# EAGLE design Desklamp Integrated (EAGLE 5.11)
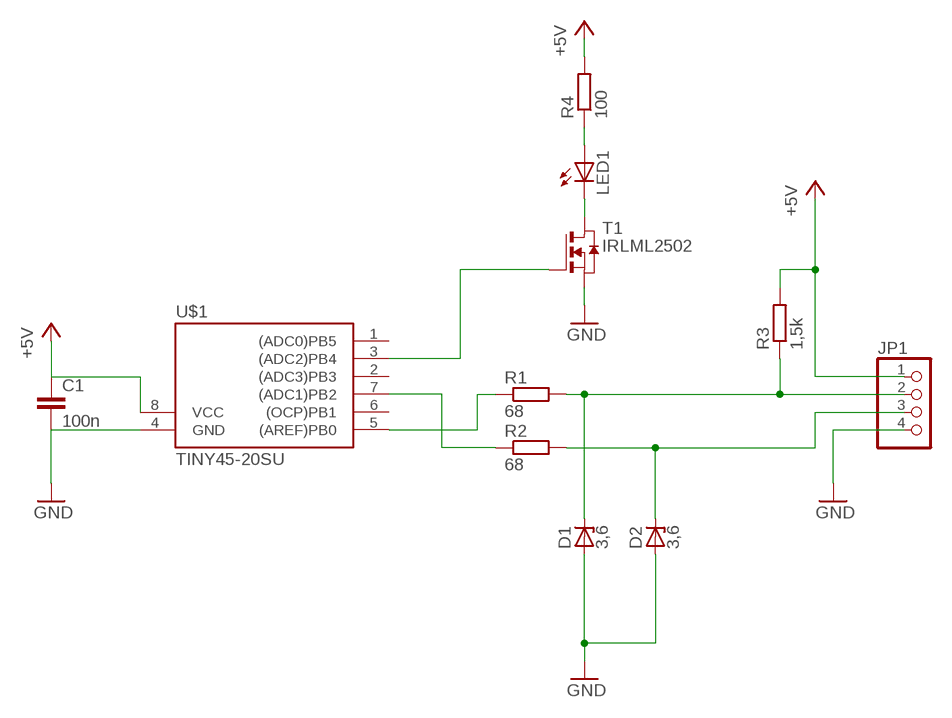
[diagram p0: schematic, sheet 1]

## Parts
C1  100n  C-EUC1206  [C1206]
D1  3,6  ZENER-DIODESOD80C  [SOD80C]
D2  3,6  ZENER-DIODESOD80C  [SOD80C]
JP1  PINHD-1X4  [1X04]
LED1  LED5MM  [LED5MM]
R1  68  R-EU_M1206  [M1206]
R2  68  R-EU_M1206  [M1206]
R3  1,5k  R-EU_M1206  [M1206]
R4  100  R-EU_M1206  [M1206]
T1  IRLML2502  NMOSSOT23  [SOT-23]
U$1  TINY45-20SU  TINY25/45/85-20SU  [SOIC8]

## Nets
+5V: C1.1 JP1.1 R3.2 R4.2 U$1.8(VCC)
GND: C1.2 D1.A D2.A JP1.4 T1.2(S) U$1.4(GND)
N$1: T1.3(G) U$1.3((ADC2)PB4)
N$2: LED1.K(C) T1.1(D)
N$3: LED1.A R4.1
N$6: R1.1 U$1.5((AREF)PB0)
N$7: D1.C JP1.2 R1.2 R3.1
N$8: D2.C JP1.3 R2.2
N$9: R2.1 U$1.7((ADC1)PB2)
Unconnected: U$1.1((ADC0)PB5) U$1.2((ADC3)PB3) U$1.6((OCP)PB1)

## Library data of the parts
C1 = rcl:C-EU: CAPACITOR, European symbol
D1 D2 = diode:ZENER-DIODE: Z-Diode
JP1 = pinhead:PINHD-1X4: PIN HEADER
LED1 = led:LED: LED
R1-R4 = rcl:R-EU_: RESISTOR, European symbol
T1 = zetex:NMOSSOT23: MOS FET; OC_FARNELL: unknown; OC_NEWARK: unknown
U$1 = avr-6:TINY25/45/85

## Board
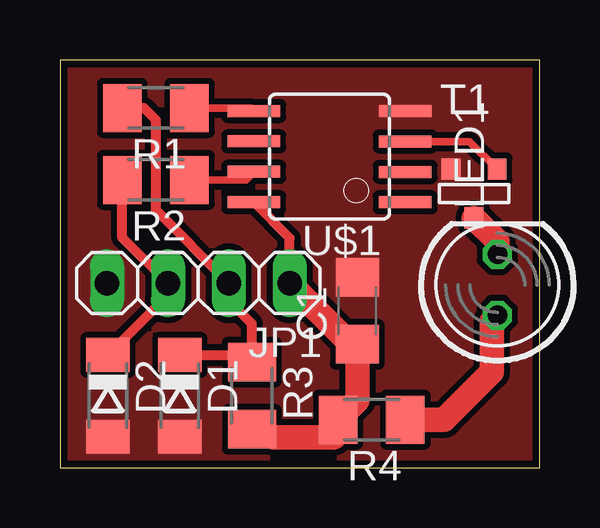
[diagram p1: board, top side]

Size 20 x 17 mm. Coordinates in mm from the lower left corner, seen from the top.
Outline: 0,0 20,0 20,17 0,17 0,0
Copper layers (1*16): Top 0.035mm / dielectric 1.5mm / Bottom 0.035mm
Design rules "PCB-POOL Standard": minimum track width 0.15mm, minimum drill 0.3mm, track to track 0.15mm, track to pad 0.15mm, pad to pad 0.15mm, via to via 0.15mm, smd to smd 0.15mm, copper to edge 0.3mm, drill to drill 0.2mm, minimum pad ring 0.2mm, minimum via ring 0.15mm, stop-mask expansion 0.075mm, vias tented up to drill 0mil, thermal gap 0.2mm

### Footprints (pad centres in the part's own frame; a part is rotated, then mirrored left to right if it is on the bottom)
C1206 = smd 1.6 x 1.8: 1 -1.4,0; 2 1.4,0
SOD80C = smd 1.4 x 1.8: A 1.7,0; C -1.7,0
1X04 = drill 1.016 long: 1 -3.81,0; 2 -1.27,0; 3 1.27,0; 4 3.81,0
LED5MM = drill 0.813 octagon: A -1.27,0; K 1.27,0
M1206 = smd 1.6 x 2: 1 -1.4,0; 2 1.4,0
SOT-23 = smd 0.787 x 0.889: 1 0.025,-1.016; 2 -0.94,1.016; 3 0.991,1.016
SOIC8 = smd 0.5 x 2.2: 1 -1.905,-3.154; 2 -0.645,-3.154; 3 0.625,-3.154; 4 1.895,-3.154; 5 1.905,3.154; 6 0.635,3.154; 7 -0.635,3.154; 8 -1.905,3.154

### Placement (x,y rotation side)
C1  12.4,6.54 90 top
D1  5,3 270 top
D2  2,3 270 top
JP1  5.77,7.69 180 top
LED1  18.24,7.62 90 top
R1  4,15 180 top
R2  4,12 180 top
R3  8,3 270 top
R4  13,2 180 top
T1  17.24,11.43 0 top
U$1  11.24,12.97 90 top

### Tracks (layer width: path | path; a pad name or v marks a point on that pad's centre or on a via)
+5V
  Top 0.254: R3.2 8.89,1.27 | 11.43,1.27 R4.2 | C1.1 12.7,5.08
  Top 0.406: JP1.1 9.58,9.57 U$1.8
  Top 1.016: R4.2 12.4,2.8 C1.1 12.13,5.14 JP1.1 | 8.89,1.27 11.43,1.27
GND
  pour Top (isolate 0.254, no thermals): 0,17 20,17 20,0 0,0
  pour Top (isolate 0.254, no thermals): 0,0 20,0 20,17 0,17
N$1
  Top 0.305: U$1.3 17.08,13.6 T1.3
N$2
  Top 1.016: LED1.K 18.24,9.44 T1.1
N$3
  Top 1.016: R4.1 16,2 18,4 18,6.11 LED1.A
N$6
  Top 0.305: R1.1 7.96,15 U$1.5
N$7
  Top 0.406: D1.C 7.7,4.7 R3.1 8,6 7.04,6.96 JP1.2 4,10.73 4,14.5 3.5,15 R1.2
N$8
  Top 0.406: R2.2 2.6,9.59 JP1.3 4.5,7.2 D2.C
N$9
  Top 0.305: R2.1 7.75,12 U$1.7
